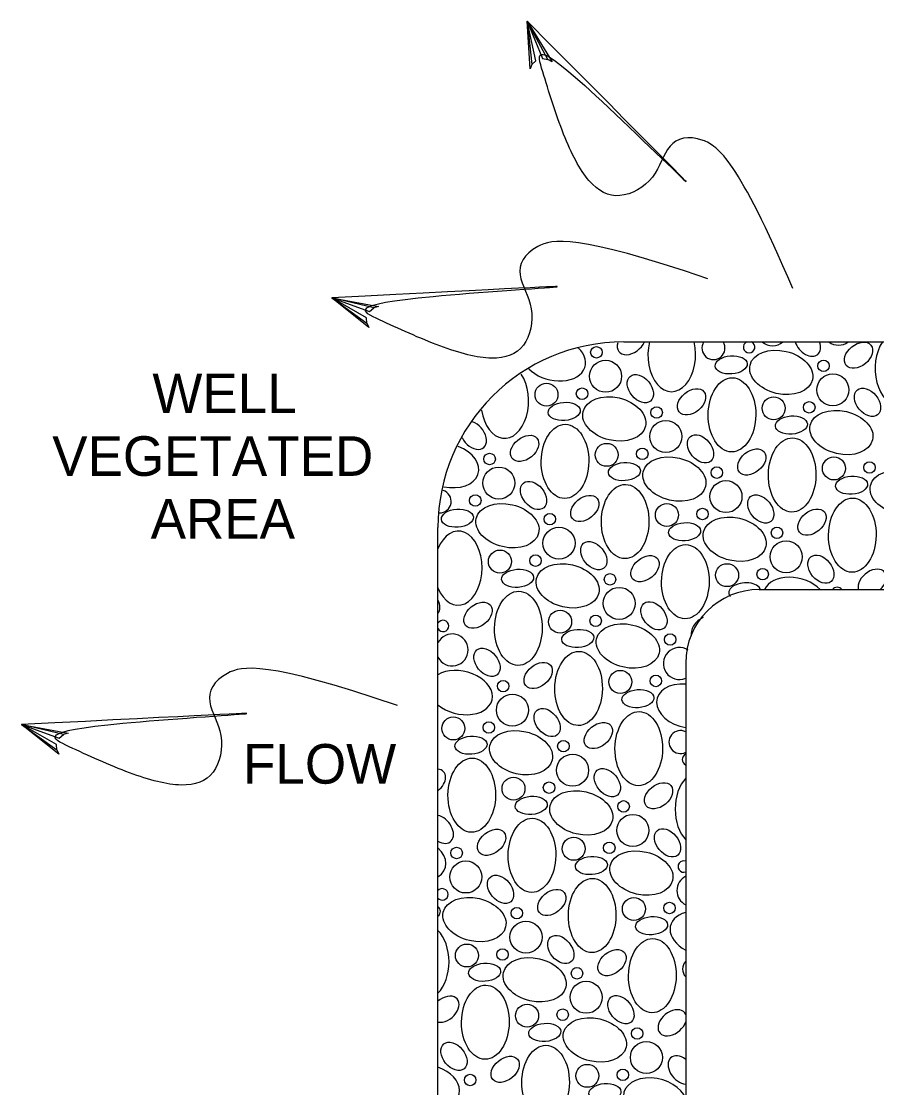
# Model space of a CAD drawing. Extents: x 636462 to 637367, y 299944 to 300538.
# Drawn here: x 636731 to 636795.7, y 300304.9 to 300385.6 of the extents above; entities that cross this region are included whole.
import ezdxf

# ---------------------------------------------------------------- set-up
doc = ezdxf.new("R2010")
doc.units = 0
doc.layers.add('Default', color=7, linetype='Continuous')

msp = doc.modelspace()

# ---------------------------------------------------------------- linework, layer by layer
at = {"layer": 'Default'}
for p, q in [((636786.81, 300342.561), (636859.157, 300342.561)), ((636781.245, 300336.996), (636781.245, 300292.475))]:
    msp.add_line(p, q, dxfattribs=at)
for points in [[(636769.606, 300382.283), (636769.472, 300381.96), (636769.26, 300385.559), (636769.606, 300382.283), (636769.904, 300382.581), (636769.26, 300385.559), (636770.403, 300382.741), (636770.815, 300382.678), (636769.26, 300385.559), (636771.141, 300382.483), (636770.815, 300382.678)], [(636757.134, 300362.706), (636757.284, 300362.39), (636754.47, 300364.644), (636757.134, 300362.706), (636757.112, 300363.127), (636754.47, 300364.644), (636757.327, 300363.604), (636757.65, 300363.868), (636754.47, 300364.644), (636758.013, 300363.98), (636757.65, 300363.868)], [(636776.561, 300361.299), (636869.406, 300361.299)], [(636762.507, 300282.226), (636762.507, 300347.245)], [(636733.675, 300330.419), (636733.827, 300330.104), (636730.998, 300332.339), (636733.675, 300330.419), (636733.651, 300330.84), (636730.998, 300332.339), (636733.862, 300331.319), (636734.184, 300331.585), (636730.998, 300332.339), (636734.546, 300331.698), (636734.184, 300331.585)]]:
    msp.add_lwpolyline(points, dxfattribs=at)
for centre, radius in [((636774.492, 300360.512), 0.435), ((636775.188, 300358.695), 1.211), ((636791.674, 300359.484), 0.435), ((636792.37, 300357.667), 1.211), ((636770.718, 300357.305), 0.869), ((636773.409, 300357.378), 0.435), ((636787.9, 300356.277), 0.869), ((636779.045, 300355.96), 0.435), ((636790.591, 300356.349), 0.435), ((636779.74, 300354.142), 1.211), ((636775.27, 300352.752), 0.869), ((636777.962, 300352.825), 0.435), ((636766.415, 300352.436), 0.435), ((636792.453, 300351.724), 0.869), ((636795.144, 300351.797), 0.435), ((636767.111, 300350.618), 1.211), ((636783.597, 300351.407), 0.435), ((636784.293, 300349.59), 1.211), ((636765.332, 300349.301), 0.435), ((636779.823, 300348.2), 0.869), ((636770.968, 300347.883), 0.435), ((636782.514, 300348.273), 0.435), ((636771.663, 300346.065), 1.211), ((636788.15, 300346.855), 0.435), ((636788.845, 300345.037), 1.211), ((636767.194, 300344.675), 0.869), ((636769.885, 300344.748), 0.435), ((636784.376, 300343.647), 0.869), ((636787.067, 300343.72), 0.435), ((636775.52, 300343.33), 0.435), ((636776.216, 300341.513), 1.211), ((636771.746, 300340.123), 0.869), ((636774.437, 300340.196), 0.435), ((636780.073, 300338.778), 0.435), ((636776.299, 300335.57), 0.869), ((636778.99, 300335.643), 0.435), ((636767.444, 300335.253), 0.435), ((636768.139, 300333.436), 1.211), ((636763.669, 300332.046), 0.869), ((636766.36, 300332.119), 0.435), ((636771.996, 300330.701), 0.435), ((636772.691, 300328.883), 1.211), ((636768.222, 300327.493), 0.869), ((636770.913, 300327.566), 0.435), ((636776.549, 300326.148), 0.435), ((636777.244, 300324.331), 1.211), ((636763.919, 300322.624), 0.435), ((636772.774, 300322.941), 0.869), ((636775.465, 300323.014), 0.435), ((636764.614, 300320.806), 1.211), ((636777.327, 300318.388), 0.869), ((636768.472, 300318.071), 0.435), ((636780.018, 300318.461), 0.435), ((636769.167, 300316.254), 1.211), ((636764.697, 300314.864), 0.869), ((636767.388, 300314.937), 0.435), ((636773.024, 300313.519), 0.435), ((636773.719, 300311.701), 1.211), ((636769.25, 300310.311), 0.869), ((636771.941, 300310.384), 0.435), ((636777.577, 300308.966), 0.435), ((636778.272, 300307.149), 1.211), ((636773.802, 300305.759), 0.869), ((636776.494, 300305.831), 0.435), ((636764.947, 300305.442), 0.435)]:
    msp.add_circle(centre, radius, dxfattribs=at)
for centre, radius, start, end in [((636776.561, 300347.245), 14.053, 90, 180), ((636783.347, 300360.829), 0.869, 147.31144, 32.68856), ((636786.039, 300360.902), 0.435, 114.11117, 65.88883), ((636787.817, 300362.219), 1.211, 229.45601, 310.54399), ((636762.641, 300349.228), 0.869, 268.10836, 72.71412), ((636786.81, 300336.996), 5.565, 90, 180), ((636792.703, 300342.302), 0.435, 36.5409, 143.4591), ((636762.891, 300339.806), 0.435, 208.04198, 151.95802), ((636763.586, 300337.988), 1.211, 207.05695, 152.94305), ((636780.768, 300336.96), 1.211, 56.0578, 293.18413), ((636780.851, 300331.018), 0.869, 63.04948, 296.95052), ((636781.101, 300321.596), 0.435, 70.65915, 289.34085), ((636781.796, 300319.778), 1.211, 117.0703, 242.9297), ((636762.836, 300319.489), 0.435, 220.90598, 139.09402), ((636781.879, 300313.836), 0.869, 136.85867, 223.14133)]:
    msp.add_arc(centre, radius, start, end, dxfattribs=at)
for centre, major_axis, ratio, start_param, end_param in [((636777.137, 300361.318), (0.938, 0.766), 0.672414, 2.3371, 5.381736), ((636780.193, 300360.333), (0.03, 2.806), 0.641702, 1.226141, 5.070554), ((636790.446, 300361.28), (-0.766, 0.938), 0.672414, 1.051167, 4.227986), ((636792.822, 300363.857), (0.03, 2.806), 0.641702, 2.725145, 3.57155), ((636797.375, 300359.305), (0.03, 2.806), 0.641702, 0.787152, 5.509543), ((636771.289, 300360.021), (-2.359, 0.554), 0.672414, 0.798404, 3.998552), ((636767.563, 300356.808), (0.03, 2.806), 0.641702, 1.824351, 5.534624), ((636765.187, 300354.231), (-0.766, 0.938), 0.672414, 1.234918, 5.476955), ((636763.212, 300351.944), (-2.359, 0.554), 0.672414, 1.615674, 4.514856), ((636764.039, 300344.179), (0.03, 2.806), 0.641702, 2.141325, 7.316258), ((636795.348, 300343.108), (0.938, 0.766), 0.672414, 4.817614, 9.126791), ((636789.499, 300341.81), (-2.359, 0.554), 0.672414, 3.940814, 6.155911), ((636785.714, 300342.379), (1.211, 0.089), 0.56568, 0.138133, 3.518697), ((636761.663, 300341.602), (-0.766, 0.938), 0.672414, 3.27813, 4.383089), ((636782.718, 300339.584), (0.938, 0.766), 0.672414, 1.20692, 2.831097), ((636764.24, 300334.762), (-2.359, 0.554), 0.672414, 0.915268, 5.681119), ((636781.422, 300333.733), (-2.359, 0.554), 0.672414, 4.943296, 7.936275), ((636782.19, 300329.749), (1.211, 0.089), 0.56568, 2.42329, 3.77716), ((636762.012, 300327.982), (0.938, 0.766), 0.672414, 4.691845, 6.870492), ((636782.249, 300325.969), (0.03, 2.806), 0.641702, 0.607695, 2.566702), ((636762.691, 300324.42), (-0.766, 0.938), 0.672414, 2.073989, 5.587231), ((636760.716, 300322.132), (-2.359, 0.554), 0.672414, 2.575839, 4.020547), ((636761.483, 300318.148), (1.211, 0.089), 0.56568, 5.677212, 6.806423), ((636782.451, 300316.551), (-2.359, 0.554), 0.672414, 5.398177, 7.481394), ((636761.543, 300314.367), (0.03, 2.806), 0.641702, 3.723426, 5.734156), ((636763.04, 300310.8), (0.938, 0.766), 0.672414, 3.689771, 7.872567), ((636780.222, 300309.772), (0.938, 0.766), 0.672414, 6.079345, 11.766178), ((636780.901, 300306.209), (-0.766, 0.938), 0.672414, 5.047285, 8.897119), ((636761.744, 300304.95), (-2.359, 0.554), 0.672414, 2.052765, 4.543621), ((636778.926, 300303.922), (-2.359, 0.554), 0.672414, 3.538888, 9.340684)]:
    msp.add_ellipse(centre, major_axis=major_axis, ratio=ratio, start_param=start_param, end_param=end_param, dxfattribs=at)
for centre, major_axis, ratio in [((636794.319, 300360.29), (0.938, 0.766), 0.672414), ((636784.686, 300359.561), (1.211, 0.089), 0.56568), ((636788.471, 300358.992), (-2.359, 0.554), 0.672414), ((636777.816, 300357.755), (-0.766, 0.938), 0.672414), ((636784.745, 300355.78), (0.03, 2.806), 0.641702), ((636781.69, 300356.766), (0.938, 0.766), 0.672414), ((636794.999, 300356.727), (-0.766, 0.938), 0.672414), ((636775.842, 300355.468), (-2.359, 0.554), 0.672414), ((636772.057, 300356.037), (1.211, 0.089), 0.56568), ((636793.024, 300354.44), (-2.359, 0.554), 0.672414), ((636789.239, 300355.008), (1.211, 0.089), 0.56568), ((636772.116, 300352.256), (0.03, 2.806), 0.641702), ((636769.06, 300353.241), (0.938, 0.766), 0.672414), ((636782.369, 300353.203), (-0.766, 0.938), 0.672414), ((636789.298, 300351.228), (0.03, 2.806), 0.641702), ((636786.243, 300352.213), (0.938, 0.766), 0.672414), ((636776.609, 300351.484), (1.211, 0.089), 0.56568), ((636780.394, 300350.915), (-2.359, 0.554), 0.672414), ((636797.576, 300349.887), (-2.359, 0.554), 0.672414), ((636769.74, 300349.679), (-0.766, 0.938), 0.672414), ((636776.668, 300347.703), (0.03, 2.806), 0.641702), ((636793.791, 300350.456), (1.211, 0.089), 0.56568), ((636773.613, 300348.689), (0.938, 0.766), 0.672414), ((636786.922, 300348.65), (-0.766, 0.938), 0.672414), ((636767.765, 300347.391), (-2.359, 0.554), 0.672414), ((636793.85, 300346.675), (0.03, 2.806), 0.641702), ((636763.98, 300347.96), (1.211, 0.089), 0.56568), ((636784.947, 300346.363), (-2.359, 0.554), 0.672414), ((636790.795, 300347.661), (0.938, 0.766), 0.672414), ((636781.162, 300346.931), (1.211, 0.089), 0.56568), ((636774.292, 300345.126), (-0.766, 0.938), 0.672414), ((636781.221, 300343.151), (0.03, 2.806), 0.641702), ((636778.166, 300344.136), (0.938, 0.766), 0.672414), ((636791.474, 300344.098), (-0.766, 0.938), 0.672414), ((636768.532, 300343.407), (1.211, 0.089), 0.56568), ((636772.317, 300342.839), (-2.359, 0.554), 0.672414), ((636768.591, 300339.626), (0.03, 2.806), 0.641702), ((636765.536, 300340.612), (0.938, 0.766), 0.672414), ((636778.845, 300340.573), (-0.766, 0.938), 0.672414), ((636776.87, 300338.286), (-2.359, 0.554), 0.672414), ((636773.085, 300338.855), (1.211, 0.089), 0.56568), ((636766.215, 300337.049), (-0.766, 0.938), 0.672414), ((636773.144, 300335.074), (0.03, 2.806), 0.641702), ((636770.089, 300336.059), (0.938, 0.766), 0.672414), ((636777.637, 300334.302), (1.211, 0.089), 0.56568), ((636770.768, 300332.496), (-0.766, 0.938), 0.672414), ((636777.696, 300330.521), (0.03, 2.806), 0.641702), ((636768.793, 300330.209), (-2.359, 0.554), 0.672414), ((636774.641, 300331.507), (0.938, 0.766), 0.672414), ((636765.008, 300330.778), (1.211, 0.089), 0.56568), ((636765.067, 300326.997), (0.03, 2.806), 0.641702), ((636775.32, 300327.944), (-0.766, 0.938), 0.672414), ((636779.194, 300326.954), (0.938, 0.766), 0.672414), ((636773.345, 300325.656), (-2.359, 0.554), 0.672414), ((636769.56, 300326.225), (1.211, 0.089), 0.56568), ((636769.619, 300322.444), (0.03, 2.806), 0.641702), ((636766.564, 300323.43), (0.938, 0.766), 0.672414), ((636779.873, 300323.391), (-0.766, 0.938), 0.672414), ((636774.113, 300321.672), (1.211, 0.089), 0.56568), ((636777.898, 300321.104), (-2.359, 0.554), 0.672414), ((636767.243, 300319.867), (-0.766, 0.938), 0.672414), ((636774.172, 300317.892), (0.03, 2.806), 0.641702), ((636771.117, 300318.877), (0.938, 0.766), 0.672414), ((636765.269, 300317.58), (-2.359, 0.554), 0.672414), ((636778.666, 300317.12), (1.211, 0.089), 0.56568), ((636771.796, 300315.314), (-0.766, 0.938), 0.672414), ((636778.725, 300313.339), (0.03, 2.806), 0.641702), ((636775.669, 300314.325), (0.938, 0.766), 0.672414), ((636766.036, 300313.596), (1.211, 0.089), 0.56568), ((636769.821, 300313.027), (-2.359, 0.554), 0.672414), ((636766.095, 300309.815), (0.03, 2.806), 0.641702), ((636776.348, 300310.762), (-0.766, 0.938), 0.672414), ((636774.374, 300308.474), (-2.359, 0.554), 0.672414), ((636770.589, 300309.043), (1.211, 0.089), 0.56568), ((636763.719, 300307.237), (-0.766, 0.938), 0.672414), ((636770.648, 300305.262), (0.03, 2.806), 0.641702), ((636767.592, 300306.248), (0.938, 0.766), 0.672414), ((636775.141, 300304.49), (1.211, 0.089), 0.56568)]:
    msp.add_ellipse(centre, major_axis=major_axis, ratio=ratio, dxfattribs=at)
for points in [[(636789.339, 300365.342), (636785.199, 300375.049), (636782.223, 300377.216), (636779.76, 300376.459), (636779.11, 300373.562), (636776.16, 300371.885), (636773.859, 300373.104), (636771.966, 300376.759), (636770.342, 300382.039), (636769.26, 300385.559), (636789.339, 300365.342), (636769.26, 300385.559)], [(636782.926, 300366.084), (636772.937, 300369.487), (636769.336, 300368.718), (636768.255, 300366.38), (636769.977, 300363.961), (636769.255, 300360.645), (636766.811, 300359.748), (636762.825, 300360.78), (636757.812, 300363.098), (636754.47, 300364.644), (636782.926, 300366.084), (636754.47, 300364.644)], [(636759.455, 300333.779), (636749.466, 300337.182), (636745.865, 300336.413), (636744.783, 300334.075), (636746.505, 300331.656), (636745.783, 300328.34), (636743.339, 300327.443), (636739.354, 300328.475), (636734.34, 300330.793), (636730.998, 300332.339), (636759.455, 300333.779), (636730.998, 300332.339)]]:
    msp.add_open_spline(points, degree=3, dxfattribs=at)

# ---------------------------------------------------------------- texts
for s, p in [('WELL', (636740.91, 300355.908)), ('VEGETATED', (636733.332, 300351.161)), ('AREA', (636740.78, 300346.414)), ('FLOW', (636747.768, 300327.869))]:
    msp.add_text(s, height=2.998, dxfattribs=at).set_placement(p)

doc.saveas('drawing.dxf')
